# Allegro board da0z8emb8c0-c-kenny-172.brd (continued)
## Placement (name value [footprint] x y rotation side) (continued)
R444  *Short_0603  [S0603]  118.1 18.15 270 top
R445  *Short_0603  [S0603]  119.52 18.15 270 top
R446  *4.7K_5%_2  [R0201]  206.18 17.39 180 top
R448  *TPM@10K_1%_2  [R0201]  121.09 16.75 90 top
R450  *Short_0201  [S0201]  71.94 16.12 0 top
R451  4.7K_5%_2  [R0201]  204.66 17.39 180 top
R452  *TPM@0_5%_6  [R0603]  132.95 18.15 180 top
R453  *TPM@0_5%_6  [R0603]  132.95 19.67 180 top
R458  *TPM@33_5%_2  [R0201]  121.85 16.75 90 top
R459  100K_5%_2  [R0201]  183.58 18.53 0 top
R460  4.7K_5%_2  [R0201]  206.18 16.5 180 top
R461  *4.7K_5%_2  [R0201]  204.66 16.5 180 top
R462  100K_5%_2  [R0201]  164.02 17.26 90 top
R463  *10K_1%_2  [R0201]  127.44 16.12 180 top
R464  *GS@0_5%_2  [R0201]  67.96 18.15 180 top
R465  *4.7K_5%_2  [R0201]  204.66 15.61 180 top
R466  4.7K_5%_2  [R0201]  206.18 15.61 180 top
R468  *GS@10K_1%_2  [R0201]  67.56 15.73 0 top
R469  4.7K_5%_2  [R0201]  71.05 20.94 180 top
R470  *4.7K_5%_2  [R0201]  204.66 14.72 180 top
R471  4.7K_5%_2  [R0201]  206.18 14.72 180 top
R475  *GS@0_5%_2  [R0201]  67.78 14.87 90 top
R476  *4.7K_5%_2  [R0201]  204.66 13.83 180 top
R477  4.7K_5%_2  [R0201]  206.18 13.83 180 top
R481  4.7K_5%_2  [R0201]  204.66 12.81 180 top
R483  *GS@10K_1%_2  [R0201]  64.83 15.1 270 top
R484  *GS@0_5%_2  [R0201]  64.07 15.1 270 top
R485  *4.7K_5%_2  [R0201]  206.18 12.81 180 top
R486  *TPC@0_5%_2  [R0201]  11.31 11.8 0 top
R487  33_5%_2  [R0201]  183.58 15.1 0 top
R488  *Short_0201  [S0201]  203.13 14.59 180 top
R489  *TPC@0_5%_2  [R0201]  11.31 10.63 0 top
R492  *SSD@10K_5%_2  [R0201]  23.43 9 0 top
R497  *Short_0201  [S0201]  29.14 4.18 270 top
R498  *Short_0201  [S0201]  31.43 3.54 180 top
R500  *Short_0805  [S0805]  24.95 3.03 0 top
R501  *SSD@100K_1%_2  [R0201]  31.43 2.78 0 top
R507  2.2_5%_0603  [R0603]  43.37 121.53 0 bottom
R514  *Short_0201  [S0201]  39.69 115.18 0 bottom
R515  *Short_0805  [S0805]  64.45 109.59 270 top
R516  33_5%_2  [R0201]  59.14 109.92 270 top
R517  33_5%_2  [R0201]  56.15 105.02 90 bottom
R518  0_5%_6  [R0603]  58.99 104.84 270 bottom
R519  *0_5%_2  [R0201]  44.38 103.62 270 bottom
R520  *0_5%_2  [R0201]  45.15 103.62 270 bottom
R521  0_5%_2  [R0201]  46.42 105.02 270 bottom
R522  0_5%_2  [R0201]  47.18 105.02 270 bottom
R535  100K_1%_2  [R0201]  68.51 91.17 270 bottom
R536  *Short_0201  [S0201]  68.51 92.19 90 bottom
R551  *HUB@10K_4  [R0402]  95.18 91.3 270 bottom
R552  *HUB@10K_4  [R0402]  96.2 91.3 270 bottom
R554  *HDT@1K_1%_2  [R0201]  120.84 50.15 0 bottom
R556  *HUB@10K_4  [R0402]  100.52 88.89 180 bottom
R559  *HUB@100K_1%_4  [R0402]  101.15 87.49 90 bottom
R560  *HDT@10K_1%_2  [R0201]  120.84 47.87 180 bottom
R563  *HUB@10K_4  [R0402]  101.8 86.05 180 bottom
R566  *HUB@10K__5%_4  [R0402]  101.8 84.91 180 bottom
R567  *HDT@33_5%_2  [R0201]  111.85 43.04 90 bottom
R568  *HDT@1K_1%_2  [R0201]  117.89 47.61 180 top
R569  *HDT@1K_1%_2  [R0201]  117.89 45.83 180 top
R570  *0_5%_4  [R0402]  208.21 16.5 0 bottom
R571  *HUB@619_1%_4  [R0402]  93.28 82.92 270 bottom
R573  *33K_1%_4  [R0402]  212.13 15.48 0 bottom
R575  *HDT@10K_1%_2  [R0201]  120.94 46.34 180 bottom
R589  *150_1%_2  [R0201]  15.81 75.93 270 bottom
R595  *150_1%_2  [R0201]  16.06 81.9 270 bottom
R601  *150_1%_2  [R0201]  15.81 79.36 270 bottom
R606  *150_1%_2  [R0201]  15.81 77.71 270 bottom
R622  0_5%_2  [R0201]  19.24 57.39 0 bottom
R626  *HDT@1K_1%_2  [R0201]  111.44 49.26 180 bottom
R646  *0_5%_8  [R0805]  17.59 49.14 90 bottom
R649  *0_5%_8  [R0805]  21.78 49.14 90 bottom
R686  100K_5%_2  [R0201]  208.72 28.69 180 bottom
R690  *Short_0402  [S0402]  203.64 17.51 270 top
R691  *0_5%_2  [R0201]  209.74 31.1 0 top
R694  *0_5%_4  [R0402]  205.17 35.17 90 bottom
R695  *Short_0603  [S0603]  204.81 32.96 270 bottom
R697  *Short_0402  [S0402]  204.15 35.17 270 bottom
R698  *10K_1%_2  [R0201]  158.47 29.96 270 top
R699  *Short_0201  [S0201]  199.32 34.4 180 bottom
R700  *10K_1%_2  [R0201]  162.11 23.35 180 bottom
R706  *DBG@0_2  [R0201]  193.25 15.43 90 bottom
R707  22K_5%_2  [R0201]  200.34 34.4 180 bottom
R712  *DBG@0_2  [R0201]  192.54 15.43 90 bottom
R715  200K_1%_4  [R0402]  200.72 31.36 180 bottom
R718  10K_1%_2  [R0201]  201.23 34.53 270 bottom
R720  *0_5%_2  [R0201]  201.99 32.29 90 top
R730  MD@10K_5%_2  [R0201]  105.34 42.15 180 top
R731  MD@10K_5%_2  [R0201]  107.76 41.9 90 top
R732  MD@10K_5%_2  [R0201]  107.76 43.04 90 top
R734  100K_5%_2  [R0201]  199.99 32.37 90 bottom
R738  *Short_0805  [S0805]  189.67 29.7 180 top
R745  *Short_0201  [S0201]  195.26 23.61 90 bottom
R746  *0_5%_2  [R0201]  197.8 30.34 180 bottom
R749  22_5%_2  [R0201]  196.15 23.53 0 bottom
R751  33_5%_2  [R0201]  195.9 28.31 180 bottom
R752  *100K_1%_2  [R0201]  197.8 23.86 180 top
R754  *0_5%_2  [R0201]  197.8 29.58 180 bottom
R756  *3.3K_5%_2  [R0201]  197.93 31.1 180 bottom
R763  MD@10K_5%_2  [R0201]  106.23 41.9 90 top
R769  *0_5%_8  [R0805]  191.32 31.86 180 top
R772  *3.3K_5%_2  [R0201]  196.66 29.7 180 bottom
R773  *TPC@0_5%_6  [R0603]  32.57 18.27 90 top
R775  *TPC@10K_5%_2  [R0201]  31.43 17.64 270 top
R780  *Short_0603  [S0603]  199.83 19.87 180 top
R782  *Short_0201  [S0201]  197.8 28.82 0 bottom
R784  4.7K_5%_2  [R0201]  72.32 24.62 270 bottom
R785  *TPC@10K_5%_2  [R0201]  31.43 18.78 270 top
R787  4.7K_5%_2  [R0201]  75.5 24.62 270 bottom
R791  *10K_1%_2  [R0201]  168.34 21.07 0 bottom
R794  *2.2_5%_0603  [R0603]  167.57 23.74 0 bottom
R795  *10K_5%_2  [R0201]  67.12 22.44 90 bottom
R796  *Short_0201  [S0201]  68.01 22.21 180 bottom
R797  10K_5%_2  [R0201]  70.29 23.48 270 bottom
R798  *Short_0201  [S0201]  71.05 24.12 270 bottom
R802  *0_5%_2  [R0201]  192.59 19.67 90 bottom
R803  *2.2_5%_0603  [R0603]  164.94 23.74 180 bottom
R804  *PBA@0_5%_2  [R0201]  55.79 21.65 0 bottom
R805  4.7K_5%_2  [R0201]  174.22 32.12 90 top
R806  *10K_1%_2  [R0201]  124.27 17 180 bottom
R807  *Short_0201  [S0201]  70.42 25.77 0 bottom
R810  *0_5%_8  [R0805]  123.84 19.16 180 bottom
R811  4.7K_5%_2  [R0201]  173.09 32.42 0 top
R812  *33_5%_2  [R0201]  124.27 16.24 180 bottom
R816  4.7K_5%_2  [R0201]  181.29 18.53 180 bottom
R817  *TPC@10K_5%_2  [R0201]  26.35 18.27 270 top
R818  *TPC@0_5%_6  [R0603]  13.78 21.7 0 bottom
R819  *Short_0201  [S0201]  192.72 18.66 270 bottom
R820  *Short_0201  [S0201]  71.28 25.01 180 bottom
R824  *TPC@10K_5%_2  [R0201]  26.35 17.26 270 top
R825  *10K_1%_2  [R0201]  187.89 23.86 0 top
R827  *10K_1%_2  [R0201]  197.27 18.05 270 bottom
R828  *10K_1%_2  [R0201]  189.04 15.73 0 top
R830  *DBG@0_5%_2  [R0201]  192.72 17.64 90 bottom
R833  4.7K_5%_2  [R0201]  181.29 17.64 180 bottom
R834  GS_N@0_5%_2  [R0201]  212.41 17.39 180 bottom
R835  *GS@0_5%_2  [R0201]  212.41 16.62 180 bottom
R837  *Short_0201  [S0201]  212.28 13.96 90 bottom
R843  *Short_0201  [S0201]  32.22 11.64 90 bottom
R844  *Short_0201  [S0201]  32.98 11.64 90 bottom
R845  *Short_0201  [S0201]  35.22 11.64 90 bottom
R846  *Short_0201  [S0201]  35.98 11.64 90 bottom
R847  *Short_0201  [S0201]  26.22 11.54 90 bottom
R848  *Short_0201  [S0201]  26.99 11.54 90 bottom
R849  *Short_0201  [S0201]  29.22 11.54 90 bottom
R850  *Short_0201  [S0201]  29.98 11.54 90 bottom
R851  *Short_0201  [S0201]  38.24 11.54 90 bottom
R852  *Short_0201  [S0201]  39 11.54 90 bottom
R2211  *EV@5.1K_1%_2  [R0201]  120.97 120.38 270 top
R2212  *EV@5.1K_1%_2  [R0201]  121.6 125.08 270 top
R2213  EV@5.1K_1%_2  [R0201]  123.25 123.56 270 top
R2214  EV@5.1K_1%_2  [R0201]  122.49 121.02 270 top
R2215  EV@10K_5%_2  [R0201]  119.95 125.21 0 top
R2216  EV@10K_5%_2  [R0201]  120.08 122.54 0 top
R2217  EV@4.7K_5%_2  [R0201]  118.65 123.66 270 top
R2218  EV@5.1K_1%_2  [R0201]  120.97 122.03 270 top
R2219  EV@5.1K_1%_2  [R0201]  121.6 123.56 270 top
R2220  *EV@5.1K_1%_2  [R0201]  122.49 123.56 270 top
R2221  *EV@5.1K_1%_2  [R0201]  122.74 119.49 270 top
R2222  EV@10_1%_2  [R0201]  124.65 119.49 180 top
R2223  EV@49.9/F_2  [R0201]  124.52 121.78 90 top
R2226  EV@33_5%_2  [R0201]  119.95 124.45 180 top
R2227  EV@4.7K_5%_2  [R0201]  118.65 125.08 90 top
R2229  EV@10K_5%_2  [R0201]  113.85 118.99 90 top
R2230  EV@10K_5%_2  [R0201]  115.12 118.99 90 top
R2231  EV@33_5%_2  [R0201]  120.08 121.78 180 top
R2232  EV@5.1K_1%_2  [R0201]  124.65 118.73 180 top
R2236  EV@5.49K_1%_2  [R0201]  139.38 117.21 0 top
R2237  EV@2.37K_1%_2  [R0201]  141.29 116.95 180 top
R2238  EV@60.4_1%_2  [R0201]  142.17 113.4 180 top
R2239  EV@60.4_1%_2  [R0201]  142.17 112.64 180 top
R2240  EV@1K_1%_2  [R0201]  143.39 111.38 0 top
R2241  *Short_0201  [S0201]  95.82 100.95 180 top
R2242  *Short_0201  [S0201]  95.82 100.19 180 top
R2243  *Short_0201  [S0201]  95.82 99.43 180 top
R2253  EV@1K_1%_2  [R0201]  143.35 87.19 270 top
R2254  EV@60.4_1%_2  [R0201]  142.17 85.33 180 top
R2257  EV@60.4_1%_2  [R0201]  142.17 84.57 180 top
R2270  1K_1%_2  [R0201]  51.62 52.18 0 top
R2276  1K_1%_2  [R0201]  50.23 53.2 0 top
R2283  *0_5%_2  [R0201]  55.18 58.91 0 top
R2284  1K_1%_2  [R0201]  48.19 62.98 180 top
R2290  *1K_1%_2  [R0201]  51.88 67.68 0 top
R2300  240_1%_2  [R0201]  42.1 65.66 270 top
R2301  0_5%_2  [R0201]  42.94 65.66 90 top
R2302  39_1%_2  [R0201]  33.34 90.28 270 top
R2303  39_1%_2  [R0201]  31.81 90.28 270 top
R2304  39_1%_2  [R0201]  30.54 88.76 0 top
R2306  *0_5%_2  [R0201]  105.65 33.9 90 bottom
R2307  *Short_0201  [S0201]  104.91 33.64 270 bottom
R2308  10K_1%_2  [R0201]  105.85 35.17 90 bottom
R2309  10K_1%_2  [R0201]  114.49 39.99 180 top
R2310  *2K_1%_2  [R0201]  104.96 35.8 180 bottom
R2311  *2K_1%_2  [R0201]  114.49 39.23 0 top
R2313  39_1%_2  [R0201]  30.54 88 0 top
R2314  39_1%_2  [R0201]  32.57 90.28 270 top
R2315  39_1%_2  [R0201]  30.54 87.24 0 top
R2316  39_1%_2  [R0201]  34.1 90.28 270 top
R2317  39_1%_2  [R0201]  35.62 90.28 270 top
R2318  39_1%_2  [R0201]  36.38 90.28 270 top
R2319  39_1%_2  [R0201]  37.91 90.28 270 top
R2320  39_1%_2  [R0201]  37.15 90.28 270 top
R2321  39_1%_2  [R0201]  38.67 90.28 270 top
R2322  39_1%_2  [R0201]  39.43 90.28 270 top
R2328  39_1%_2  [R0201]  30.54 85.71 0 top
R2329  39_1%_2  [R0201]  30.54 84.95 0 top
R2330  39_1%_2  [R0201]  29.91 81.14 0 top
R2332  39_1%_2  [R0201]  30.54 81.9 0 top
R2334  39_1%_2  [R0201]  30.54 79.62 0 top
R2335  39_1%_2  [R0201]  30.54 80.38 0 top
R2336  39_1%_2  [R0201]  30.54 82.66 0 top
R2337  39_1%_2  [R0201]  30.54 83.43 0 top
R2338  240_1%_2  [R0201]  43.11 78.85 270 top
R2339  0_5%_2  [R0201]  45.02 78.09 180 top
R2342  39_1%_2  [R0201]  30.54 86.47 0 top
R2343  39_1%_2  [R0201]  34.86 90.28 270 top
R2344  *39_1%_2  [R0201]  33.84 77.96 0 top
R2346  *0_5%_2  [R0201]  37.78 78.78 180 top
R2347  39_1%_2  [R0201]  30.54 84.19 0 top
R2349  10K_5%_2  [R0201]  122.62 51.42 270 top
R2350  *10K_5%_2  [R0201]  122.62 52.44 270 top
R2351  10K_5%_2  [R0201]  121.85 51.8 270 top
R2352  *10K_5%_2  [R0201]  120.46 52.06 90 top
R2354  *10K_5%_2  [R0201]  120.58 51.93 0 bottom
R2355  10K_5%_2  [R0201]  120.58 51.17 0 bottom
R2357  10K_5%_2  [R0201]  87.18 34.66 270 bottom
R2358  10K_5%_2  [R0201]  88.71 33.77 270 bottom
R2359  *10K_5%_2  [R0201]  89.7 34.25 180 bottom
R2360  *10K_5%_2  [R0201]  90.82 33.77 180 bottom
R2361  10K_5%_2  [R0201]  91.37 35.8 0 bottom
R2362  *10K_5%_2  [R0201]  86.93 32.75 0 bottom
R2363  10K_5%_2  [R0201]  86.29 34.78 180 bottom
R2364  10K_5%_2  [R0201]  89.6 33.51 0 bottom
R2365  *10K_5%_2  [R0201]  90.56 34.66 270 bottom
R2376  *10K_5%_2  [R0201]  87.18 33.64 270 bottom
R2389  *Short_0603  [S0603]  50.73 50.41 90 top
R2390  100K_5%_2  [R0201]  116.77 36.56 0 top
R2391  *Short_0402  [S0402]  89.46 29.19 270 top
R2392  *Short_0402  [S0402]  81.09 25.51 270 top
R2393  *Short_0402  [S0402]  92.98 30.97 270 top
R2394  *Short_0402  [S0402]  82.1 25.51 270 top
R2395  10K_5%_2  [R0201]  103.69 32.24 90 top
R2396  470_1%_2  [R0201]  98.99 29.83 90 top
R2397  1K_1%_2  [R0201]  100.77 29.2 270 top
R2398  *Short_0402  [S0402]  93.99 31.74 270 top
R2399  *0_5%_2  [R0201]  96.71 34.28 0 top
R2400  47K_1%_2  [R0201]  91.27 27.72 270 bottom
R2401  *Short_0201  [S0201]  111.12 52.87 90 bottom
R2402  *Short_0201  [S0201]  111.89 52.87 90 bottom
R2403  *0_5%_2  [R0201]  106.36 34.15 270 bottom
R2404  1M_5%_2  [R0201]  105.98 38.59 90 bottom
R2406  8.2K_5%_4  [R0402]  115.25 36.56 180 top
R2407  *Short_0201  [S0201]  114.11 37.43 0 top
R2408  20M_5%_4  [R0402]  107.38 41.9 90 bottom
R2409  *Short_0603  [S0603]  117.03 42.53 270 top
R2410  *Short_0603  [S0603]  115.23 42.53 270 top
R2411  *Short_0603  [S0603]  102.68 37.58 0 top
R2412  *Short_0402  [S0402]  102.07 35.42 0 top
R2413  *Short_0201  [S0201]  110.3 52.87 90 bottom
R2416  *Short_0201  [S0201]  108.01 51.17 0 bottom
R2418  *Short_0201  [S0201]  108.01 50.41 0 bottom
R2419  *Short_0201  [S0201]  108.01 52.95 0 bottom
R2420  *Short_0201  [S0201]  108.01 52.18 0 bottom
R2421  33_5%_2  [R0201]  98.11 36.18 90 bottom
R2425  *10K_5%_2  [R0201]  101.79 35.17 180 bottom
R2426  33_5%_2  [R0201]  108.01 48.37 0 bottom
R2427  10K_5%_2  [R0201]  103.69 35.29 270 bottom
R2428  *TPM@10K_5%_2  [R0201]  120.89 23.48 0 top
R2429  33_5%_2  [R0201]  108.01 49.14 0 bottom
R2430  *10K_5%_2  [R0201]  104.96 35.04 180 bottom
R2431  *EV@0_5%_2  [R0201]  103.95 80.89 90 bottom
R2433  *Short_0201  [S0201]  109.54 52.87 90 bottom
R2438  10K_5%_2  [R0201]  95.29 28.64 270 top
R2439  *10K_5%_2  [R0201]  115.89 48.75 90 top
R2440  10K_5%_2  [R0201]  100.14 37.2 270 top
R2443  33_5%_2  [R0201]  108.01 47.64 0 bottom
R2444  *Short_0201  [S0201]  89.09 78.73 180 bottom
R2445  *10K_5%_2  [R0201]  102.8 35.17 0 bottom
R2446  33_5%_2  [R0201]  109.15 48.75 0 bottom
R2447  10K_5%_2  [R0201]  84.52 32.24 180 bottom
R2448  10K_5%_2  [R0201]  84.9 34.28 180 bottom
R2449  *10K_5%_2  [R0201]  87.36 30.14 270 top
R2450  10K_5%_2  [R0201]  83.75 34.28 180 bottom
R2451  *10K_5%_2  [R0201]  95.69 30.72 90 bottom
R2452  *Short_0201  [S0201]  115.12 48.75 270 top
R2453  2.2K_5%_2  [R0201]  71.94 15.35 180 top
R2454  2.2K_5%_2  [R0201]  70.93 15.35 180 top
R2455  10K_5%_2  [R0201]  87.56 31.23 180 bottom
R2462  33_5%_2  [R0201]  108.27 35.42 270 bottom
R2463  2.2K_5%_2  [R0201]  84.9 35.04 180 bottom
R2464  2.2K_5%_2  [R0201]  83.5 35.29 270 bottom
R2465  10K_5%_2  [R0201]  84.52 33.01 180 bottom
R2496  *Short_0201  [S0201]  90.49 78.35 90 bottom
R2499  1K_5%_2  [R0201]  107.12 74.66 270 bottom
R2502  *220_5%_2  [R0201]  94.93 78.98 90 bottom
R2503  *220_5%_2  [R0201]  110.55 46.46 0 bottom
R2505  *220_5%_2  [R0201]  96.07 78.98 90 bottom
R2508  *Short_0201  [S0201]  91.25 78.35 90 bottom
R2509  196_1%_4  [R0402]  103.82 58.91 180 top
R2510  *1K_1%_2  [R0201]  94.55 28.64 90 top
R2511  *1K_1%_2  [R0201]  93.91 77.96 180 bottom
R2512  *1K_1%_2  [R0201]  95.95 77.96 180 bottom
R2513  *1K_1%_2  [R0201]  94.93 77.96 180 bottom
R2514  *Short_0201  [S0201]  93.91 77.2 180 bottom
R2515  *Short_0201  [S0201]  95.95 77.2 180 bottom
R2516  *Short_0201  [S0201]  94.93 77.2 180 bottom
R2517  *Short_0201  [S0201]  109.13 46.46 180 bottom
R2519  300_5%_4  [R0402]  110.55 45.62 0 bottom
R2520  *1K_1%_2  [R0201]  89.09 77.96 0 bottom
R2521  *0_5%_2  [R0201]  89.09 77.2 0 bottom
R2522  2.2K_5%_4  [R0402]  104.84 77.58 270 bottom
R2523  1K_1%_2  [R0201]  92.01 78.35 90 bottom
R2524  1K_5%_2  [R0201]  100.85 75.86 270 top
R2525  *Short_0201  [S0201]  92.01 77.33 90 bottom
R2526  1K_5%_2  [R0201]  84.52 31.48 0 bottom
R2527  1K_5%_2  [R0201]  111.69 75.68 180 bottom
R2538  300_5%_4  [R0402]  110.55 44.64 0 bottom
R2543  *10K_1%_2  [R0201]  90.49 77.33 90 bottom
R2544  *10K_1%_2  [R0201]  92.9 77.96 0 bottom
R2545  *10K_1%_2  [R0201]  91.25 77.33 90 bottom
R2546  2.2K_5%_4  [R0402]  112.96 38.47 90 bottom
R2547  2.2K_5%_4  [R0402]  112.71 36.94 0 bottom
R2549  1K_1%_2  [R0201]  96 78.22 45 top
R2550  *1K_1%_2  [R0201]  96.58 77.71 45 top
R2551  *10K_1%_2  [R0201]  92.9 77.2 0 bottom
R2599  EV@10K_1%_2  [R0201]  108.52 120.26 0 bottom
R2600  *EV@5.1K_1%_2  [R0201]  109.79 120.26 180 bottom
R2601  EV@10K_5%_2  [R0201]  112.46 120.51 0 bottom
R2603  EV@5.1K_1%_2  [R0201]  112.46 119.75 0 bottom
R2604  *EV@5.1K_1%_2  [R0201]  113.73 122.8 180 bottom
R2605  *EV@5.1K_1%_2  [R0201]  113.73 119.75 180 bottom
R2606  *EV@5.1K_1%_2  [R0201]  113.73 121.27 180 bottom
R2607  *EV@5.1K_1%_2  [R0201]  115.25 121.27 0 bottom
R2608  EV@5.1K_1%_2  [R0201]  115.25 119.75 0 bottom
R2609  EV@5.1K_1%_2  [R0201]  116.52 121.27 180 bottom
R2610  *EV@5.1K_1%_2  [R0201]  116.52 119.75 180 bottom
R2611  EV@5.1K_1%_2  [R0201]  118.04 119.75 0 bottom
R2612  EV@5.1K_1%_2  [R0201]  118.04 121.27 0 bottom
R2613  EV@5.1K_1%_2  [R0201]  119.31 121.27 180 bottom
R2614  EV@5.1K_1%_2  [R0201]  119.31 119.75 180 bottom
R2615  EV@5.1K_1%_2  [R0201]  121.09 119.37 180 bottom
R2616  EV@5.1K_1%_2  [R0201]  124.39 119.37 180 bottom
R2618  *EV@10K_1%_2  [R0201]  108.39 119.37 0 bottom
R2619  EV@1K_1%_2  [R0201]  109.79 119.44 180 bottom
R2620  *EV@1K_1%_2  [R0201]  112.46 121.27 0 bottom
R2622  *EV@5.1K_1%_2  [R0201]  112.46 118.99 0 bottom
R2623  *EV@5.1K_1%_2  [R0201]  113.73 122.03 180 bottom
R2624  EV@5.1K_1%_2  [R0201]  113.73 118.99 180 bottom
R2625  EV@5.1K_1%_2  [R0201]  113.73 120.51 180 bottom
R2626  EV@5.1K_1%_2  [R0201]  115.25 120.51 0 bottom
R2627  *EV@5.1K_1%_2  [R0201]  115.25 118.99 0 bottom
R2629  EV@4.7K_5%_2  [R0201]  107.5 121.83 180 bottom
R2630  EV@4.7K_5%_2  [R0201]  109.54 122.34 0 bottom
R2631  *EV@10K_1%_2  [R0201]  106.61 120.48 90 bottom
R2632  *EV@5.1K_1%_2  [R0201]  116.52 120.51 180 bottom
R2633  EV@5.1K_1%_2  [R0201]  116.52 118.99 180 bottom
R2634  EV@5.1K_1%_2  [R0201]  118.04 118.99 0 bottom
R2635  EV@5.1K_1%_2  [R0201]  118.04 120.51 0 bottom
R2636  *EV@5.1K_1%_2  [R0201]  119.31 120.51 180 bottom
R2637  EV@5.1K_1%_2  [R0201]  119.31 118.99 180 bottom
R2638  *EV@5.1K_1%_2  [R0201]  121.09 118.6 180 bottom
R2639  *EV@5.1K_1%_2  [R0201]  124.39 118.6 180 bottom
R2640  EV@120_1%_4  [R0402]  137.22 120.64 180 bottom
R2641  EV@2.37K_1%_2  [R0201]  148.98 113.02 0 top
R2642  EV@5.49K_1%_2  [R0201]  148.98 114.03 180 top
R2643  *Short_0201  [S0201]  107.63 120.97 90 bottom
R2644  *Short_0201  [S0201]  108.49 121.02 0 bottom
R2645  EV@200_1%_2  [R0201]  106.61 118.99 90 bottom
R2648  EV@1M_1%_2  [R0201]  104.46 122.41 180 bottom
R2650  EV@5.1K_1%_2  [R0201]  102.17 119.24 270 bottom
R2651  *EV@5.1K_1%_2  [R0201]  103.19 119.24 90 bottom
R2652  EV@0_5%_2  [R0201]  104.58 119.11 0 bottom
R2653  *EV@16.2K_1%_4  [R0402]  97.6 118.48 180 bottom
R2654  EV@5.49K_1%_2  [R0201]  130.24 113.4 0 bottom
R2655  EV@2.37K_1%_2  [R0201]  130.24 114.16 0 bottom
R2656  EV@33_1%_2  [R0201]  117.92 121.14 270 top
R2657  EV@33_1%_2  [R0201]  117.92 122.16 270 top
R2660  EV@5.1K_1%_2  [R0201]  107.63 123.18 0 top
R2661  *EV@5.1K_1%_2  [R0201]  108.65 122.41 180 top
R2662  EV@120_1%_4  [R0402]  118.63 98.69 270 top
R2663  EV@1K_1%_2  [R0201]  140.67 102.24 180 bottom
R2664  EV@33_1%_2  [R0201]  108.65 123.18 0 top
R2665  EV@100_1%_2  [R0201]  118.04 101.33 90 top
R2666  EV@40.2_1%_2  [R0201]  118.04 100.32 90 top
R2667  *EV@5.1K_1%_2  [R0201]  107.63 124.83 0 top
R2668  EV@5.1K_1%_2  [R0201]  108.65 124.07 180 top
R2669  EV@33_1%_2  [R0201]  108.65 124.83 0 top
R2670  *EV@1K_1%_2  [R0201]  94.42 96.89 0 bottom
R2671  EV@1K_1%_2  [R0201]  140.79 97.39 180 bottom
R2672  *EV@1K_1%_2  [R0201]  95.57 96.89 0 bottom
R2673  EV@150_1%_2  [R0201]  96.71 98.16 180 bottom
R2674  EV@2.37K_1%_2  [R0201]  130.56 90.66 0 bottom
R2675  EV@5.49K_1%_2  [R0201]  130.56 89.47 0 bottom
R2677  2.37K_1%_2  [R0201]  145.25 79.77 90 bottom
R2678  EV@5.49K_1%_2  [R0201]  146.24 79.77 90 bottom
R2679  EV@120_1%_4  [R0402]  139.92 79.48 270 bottom
R2680  EV@5.49K_1%_2  [R0201]  142.05 79.65 90 bottom
R2681  EV@2.37K_1%_2  [R0201]  143.35 79.65 90 bottom
R2682  *0_5%_6  [R0603]  50.35 56.63 90 top
R2683  1K_1%_2  [R0201]  32.83 77.96 180 top
R2684  *0_5%_2  [R0201]  43.11 92.32 270 top
R2685  0_5%_2  [R0201]  37.78 78.04 0 top
R2687  *0_5%_2  [R0201]  37.65 67.3 180 top
R2688  0_5%_2  [R0201]  36.64 67.3 180 top
R2689  240_1%_2  [R0201]  41.21 43.04 180 top
R2690  0_5%_2  [R0201]  43.37 43.04 180 top
R2691  *0_5%_2  [R0201]  37.65 43.67 180 top
R2692  0_5%_2  [R0201]  36.64 43.67 180 top
R2693  240_1%_2  [R0201]  40.45 30.85 180 top
R2694  0_5%_2  [R0201]  41.46 30.85 180 top
R2695  *0_5%_2  [R0201]  36.95 32.24 0 top
R2696  0_5%_2  [R0201]  37.94 32.24 0 top
R2697  39_1%_2  [R0201]  40.32 78.98 180 top
R2698  39_1%_2  [R0201]  40.32 78.22 180 top
R2699  *Short_0201  [S0201]  16.83 77.33 0 bottom
R2700  *Short_0201  [S0201]  16.83 78.09 0 bottom
R2701  *Short_0201  [S0201]  16.83 78.98 0 bottom
R2702  *Short_0201  [S0201]  16.83 79.74 0 bottom
R2703  *Short_0201  [S0201]  17.08 81.52 0 bottom
R2704  *Short_0201  [S0201]  17.08 82.28 0 bottom
R2705  *Short_0201  [S0201]  16.83 75.55 0 bottom
R2706  *Short_0201  [S0201]  16.83 76.31 0 bottom
R2708  4.7K_5%_2  [R0201]  21.27 73.65 270 bottom
R2709  4.7K_5%_2  [R0201]  20.38 73.65 270 bottom
R2710  *4.7K_5%_2  [R0201]  21.65 77.46 270 top
R2711  *4.7K_5%_2  [R0201]  22.16 73.65 270 bottom
R2714  *MMC@100K_5%_2  [R0201]  67.63 33.51 0 bottom
R2717  EV@0.01_1%_1206  [R1206]  111.9 100.7 270 top
R2718  *EV@0.01_1%_1206  [R1206]  95.41 117.51 310 bottom
R2719  *TPC@10K_5%_4  [R0402]  24.57 15.35 0 top
R2720  *HUB@0_5%_2  [R0201]  98.36 81.14 90 bottom
R2721  *HUB@0_5%_2  [R0201]  97.6 81.14 90 bottom
R2722  *HUB@0_5%_2  [R0201]  90.23 91.3 270 bottom
R2723  *HUB@0_5%_4  [R0402]  101.41 80.89 0 bottom
R2724  *HUB@0_5%_4  [R0402]  100.01 80.12 270 bottom
R6024  *0_5%_4  [R0402]  65.59 26.78 90 bottom
R6507  *HUB@100K_1%_4  [R0402]  91.12 91.3 270 bottom
R6508  *HUB@47K__5%_4  [R0402]  92.14 91.3 90 bottom
R6510  *TPC@10K_5%_2  [R0201]  23.81 23.64 90 top
R6511  *short_0402  [S0402]  21.52 20.18 270 top
R6512  *TPC@10K_5%_4  [R0402]  20.38 20.18 90 top
R6513  *TPC@10K_5%_4  [R0402]  19.24 20.18 270 top
R6514  *TPC@0_5%_2  [R0201]  17.08 19.93 90 top
R6515  *TPC@220K_5%_2  [R0201]  12.89 17.26 270 bottom
R6516  *1TPC@0K_5%_4  [R0402]  18.1 20.18 270 top
R6517  *TPC@220K_5%_2  [R0201]  12.89 18.27 90 bottom
R6518  *TPC@220K_5%_2  [R0201]  13.4 15.48 90 top
R6519  *TPC@6.2K_1%_2  [R0201]  24.06 17.26 0 top
R6520  *TPC@220K_5%_2  [R0201]  13.4 14.46 270 top
R6521  *TPC@200K_1%_2  [R0201]  25.59 16.37 180 top
R6522  *TPC@750K_1%_2  [R0201]  16.95 11.42 0 top
R6523  *short_0402  [S0402]  24.45 12.94 180 top
R6524  *TPC@750K_1%_2  [R0201]  15.94 11.42 180 top
R6525  *TPC@750K_1%_2  [R0201]  15.81 13.58 0 top
R6526  *TPC@750K_1%_2  [R0201]  14.79 13.58 180 top
R6527  *TPC@10K_1%_2  [R0201]  24.06 16.37 0 top
R6528  *TPC@0_5%_2  [R0201]  24.83 23.86 0 top
R6529  *TPC@0_5%_2  [R0201]  25.08 19.67 0 top
R6530  *HUB@0_5%_4  [R0402]  97.22 91.3 270 bottom
R6532  0_5%_4  [R0402]  93.04 26.66 180 bottom
R6533  22_1%_4  [R0402]  81.47 24.12 180 bottom
R6534  22_1%_4  [R0402]  81.85 22.72 270 bottom
R6535  *10K_1%_2  [R0201]  81.47 25.13 0 bottom
R6536  22_1%_4  [R0402]  93.03 25.64 0 bottom
R6538  22_1%_4  [R0402]  93.03 24.62 0 bottom
R6540  *0_5%_2  [R0201]  102.68 34.4 0 bottom
R6541  *0_5%_2  [R0201]  100.87 35.93 0 bottom
R6542  *0_5%_2  [R0201]  99.93 35.96 270 bottom
R6543  *0_5%_2  [R0201]  99.07 36.1 0 bottom
R6544  10K_1%_2  [R0201]  93.03 27.55 0 bottom
R6550  *10K_1%_2  [R0201]  92.77 23.23 0 bottom
R6552  10_1%_2  [R0201]  92.9 31.1 0 bottom
R6553  10_1%_2  [R0201]  98.99 31.74 270 bottom
R6554  10_1%_2  [R0201]  99.12 33.21 0 bottom
R6555  10_1%_2  [R0201]  89.85 31.1 0 bottom
R6556  10_1%_2  [R0201]  90.87 31.1 0 bottom
R6557  10_1%_2  [R0201]  91.88 31.1 0 bottom
R6558  10_1%_2  [R0201]  93.91 31.1 0 bottom
R6559  10_1%_2  [R0201]  97.09 30.85 0 bottom
R6560  10_1%_2  [R0201]  97.09 31.86 270 bottom
R6563  *0_5%_2  [R0201]  161.35 21.07 270 top
R6564  0_5%_2  [R0201]  158.18 19.67 180 top
R6565  0_5%_2  [R0201]  156.65 20.43 180 top
R6566  0_5%_2  [R0201]  155.38 20.23 180 top
R6567  0_5%_2  [R0201]  162.88 24.14 180 top
R6568  0_5%_2  [R0201]  163 22.47 270 top
R6569  0_5%_2  [R0201]  183.58 27.04 0 top
R6570  0_5%_2  [R0201]  161.48 26.15 270 top
R6571  0_5%_2  [R0201]  163.26 25.79 180 top
R6572  0_5%_2  [R0201]  163.51 19.67 180 bottom
R6573  *0_5%_2  [R0201]  158.18 20.43 0 top
R6574  *0_5%_2  [R0201]  156.65 19.67 0 top
R6575  *0_5%_2  [R0201]  155.38 20.94 0 top
R6576  *0_5%_2  [R0201]  162.88 24.88 0 top
R6577  *0_5%_2  [R0201]  163.76 22.47 90 top
R6578  *0_5%_2  [R0201]  163.26 26.53 0 top
R6579  *MMC@10_1%_2  [R0201]  94.04 33.77 270 bottom
R6580  *MMC@10_1%_2  [R0201]  92.39 31.86 180 bottom
R6581  *MMC@10_1%_2  [R0201]  98.11 31.86 180 bottom
R6582  *MMC@10_1%_2  [R0201]  98.26 33.39 90 bottom
R6583  *MMC@10_1%_2  [R0201]  89.34 31.86 180 bottom
R6584  *MMC@10_1%_2  [R0201]  90.36 31.86 180 bottom
R6585  *MMC@10_1%_2  [R0201]  91.37 31.86 180 bottom
R6586  *MMC@10_1%_2  [R0201]  93.41 31.86 180 bottom
R6587  *MMC@10_1%_2  [R0201]  94.75 33.77 270 bottom
R6588  *MMC@10_1%_2  [R0201]  96.33 31.86 90 bottom
R6589  *MMC@10_1%_2  [R0201]  96.79 32.75 180 bottom
R6590  100K_1%_2  [R0201]  97.22 77.2 45 top
R6593  *0_5%_2  [R0201]  30.54 89.52 0 top
R6594  10K_1%_2  [R0201]  163 30.47 0 top
R6640  *0_5%_2  [R0201]  192.72 27.67 180 bottom
R6642  *0_5%_4  [R0402]  104.96 31.99 90 bottom
R6643  *Short_0201  [S0201]  49.34 105.9 180 top
R6644  1K_1%_2  [R0201]  73.72 53.2 180 bottom
R6645  *33K_1%_4  [R0402]  210.5 14.21 0 bottom
R6646  *Short_0402  [S0402]  210.09 18.15 90 bottom
R6647  *10K_5%_2  [R0201]  88.07 30.09 270 top
R6648  *Short_0201  [S0201]  103.44 84.19 180 bottom
R6650  200K_1%_2  [R0201]  99.38 37.2 90 top
R8041  *EV@5.1K_1%_2  [R0201]  120.84 125.08 90 top
R8042  *EV@5.1K_1%_2  [R0201]  122.49 122.44 270 top
R8046  *EV@5.1K_1%_2  [R0201]  120.84 123.56 270 top
R8047  *EV@5.1K_1%_2  [R0201]  123.25 122.44 90 top
R8053  EV@10K_1%_2  [R0201]  115.25 122.03 0 bottom
R8069  *EV@10K_5%_2  [R0201]  123.63 119.49 0 top
R8103  *EV@0_5%_2  [R0201]  125.79 122.41 270 top
R8104  *EV@4.7K_5%_2  [R0201]  125.66 120.76 180 top
R8107  EV@4.7K_5%_2  [R0201]  125.66 121.53 0 top
R8118  *EV@0_5%_2  [R0201]  108.52 122.34 180 bottom
R8122  EV@47K_1%_2  [R0201]  110.42 124.83 270 bottom
R8123  *EV@0_5%_2  [R0201]  110.42 123.81 90 bottom
R8128  *EV@0_5%_2  [R0201]  108.01 125.59 0 bottom
R8133  *EV@0_5%_2  [R0201]  82.61 89.7 90 bottom
R8134  *Short_0201  [S0201]  82.61 88.68 270 bottom
R8485  EV@10K_5%_2  [R0201]  124.14 88.63 180 bottom
R8527  *EV@10K_5%_2  [R0201]  105.85 120.48 270 bottom
R8533  *Short_0201  [S0201]  105.85 118.99 270 bottom
R12293  EV@4.7K_5%_2  [R0201]  128.84 122.29 0 top
R12295  *EV@0_5%_2  [R0201]  129.09 123.18 270 top
R12296  *EV@4.7K_5%_2  [R0201]  128.84 121.55 180 top
R12313  *HDT@1K_1%_2  [R0201]  111.44 50.41 0 bottom
R12314  *HDT@1K_1%_2  [R0201]  111.39 51.14 0 bottom
R12315  *HDT@0_5%_2  [R0201]  111.44 48.5 180 bottom
R12316  *HDT@33_5%_2  [R0201]  120.84 48.63 180 bottom
R12317  *HDT@10K_1%_2  [R0201]  120.94 47.1 180 bottom
R67418  *0_5%_2  [R0201]  19.87 38.09 180 bottom
R67855  *Short_0603  [S0603]  18.48 39.23 0 bottom
R67859  EV@1K_1%_2  [R0201]  95.57 98.92 0 bottom
R77817  R18M-50@8.45K_1%_4  [R0402]  96.71 103.62 0 bottom
R77818  R18M-50@2K_1%_4  [R0402]  96.71 101.59 180 bottom
R77819  R18M-50@6.98K_1%_4  [R0402]  96.71 104.63 0 bottom
R77820  R18M-50@4.99K_1%_4  [R0402]  96.71 105.65 180 bottom
R77821  R18M-50@4.75K_1%_4  [R0402]  96.71 114.54 180 bottom
R77822  *R18M-50@0_5%_4  [R0402]  96.75 112.46 0 bottom
R77825  *R18M-50@6.98K_1%_4  [R0402]  96.76 111.37 0 bottom
R77826  *R18M-50@4.75K_1%_4  [R0402]  96.76 109.33 180 bottom
R77827  EV@40.2_1%_2  [R0201]  113.98 96.13 0 top
R77828  EV@100_1%_2  [R0201]  113.98 97.65 180 top
R77829  *EV@0_5%_2  [R0201]  105.65 121.73 90 top
R77830  *EV@0_5%_2  [R0201]  104.71 123.15 0 top
R77831  *HUB@0_5%_4  [R0402]  94.17 91.3 270 bottom
R77832  EV@10K_5%_2  [R0201]  103.19 40.5 0 top
R77833  *EV@10K_5%_2  [R0201]  104.2 40.5 0 top
R77835  *HDT@0_5%_2  [R0201]  113.6 46.09 180 top
R77836  *0_5%_2  [R0201]  12.63 11.8 0 top
R77837  *0_5%_2  [R0201]  12.63 10.63 0 top
R77838  0_5%_2  [R0201]  13.09 11.8 180 top
R77839  0_5%_2  [R0201]  13.09 10.63 180 top
R77840  *0_5%_2  [R0201]  97.47 79.64 90 bottom
R77841  *0_5%_2  [R0201]  98.49 79.64 90 bottom
R77842  *0_5%_2  [R0201]  97.47 80.09 270 bottom
R77843  *0_5%_2  [R0201]  98.49 80.09 270 bottom
R77844  *PBA@0_5%_2  [R0201]  89.85 89.87 270 bottom
R77845  *PBA@0_5%_2  [R0201]  88.83 89.87 270 bottom
R77846  *PBA@0_5%_2  [R0201]  89.85 89.42 90 bottom
R77847  *PBA@0_5%_2  [R0201]  88.83 89.42 90 bottom
R77848  *HUB@0_5%_2  [R0201]  40.45 114.29 180 bottom
R77849  *HUB@0_5%_2  [R0201]  40.45 113.52 180 bottom
R77850  EV@100K_1%_4  [R0402]  118.04 125.34 0 bottom
R77851  *EV@0_5%_2  [R0201]  177.86 21.32 270 bottom
R77852  *Short_0201  [S0201]  177.86 20.31 270 bottom
R77853  *EV@5.1K_1%_2  [R0201]  112.58 119.75 0 top
R77854  EV@5.1K_1%_2  [R0201]  112.58 118.99 0 top
R77855  *EV@5.1K_1%_2  [R0201]  118.04 122.92 270 bottom
R77856  EV@5.1K_1%_2  [R0201]  117.92 122.03 0 bottom
R77857  10K_5%_2  [R0201]  103.69 34.4 180 bottom
R77859  *0_5%_2  [R0201]  109.03 16.12 180 top
R77861  *EV@10K_1%_2  [R0201]  106.61 120.48 270 top
R77862  *10K_5%_2  [R0201]  105.09 41.01 270 top
R77863  10K_5%_2  [R0201]  104.07 41.26 0 top
R77864  100K_5%_2  [R0201]  163.51 20.43 0 bottom
R77865  EV@100K_5%_2  [R0201]  110.93 119.37 180 top
R77866  100K_1%_2  [R0201]  67.37 94.35 270 bottom
R77867  *Short_0201  [S0201]  128.38 123.18 270 top
R77868  10K_5%_2  [R0201]  107.88 17.13 90 top
R77869  *10K_5%_2  [R0201]  111.95 18.53 0 top
R77870  *10K_5%_2  [R0201]  119.7 24.37 0 bottom
R77871  0_5%_2  [R0201]  119.31 25.13 180 bottom
R77872  *10K_5%_2  [R0201]  96.07 36.71 270 bottom
R77873  10K_5%_2  [R0201]  97.22 36.31 0 bottom
R77874  *Short_0201  [S0201]  39.56 116.32 0 bottom
R77875  *Short_0201  [S0201]  39.56 117.21 0 bottom
R77876  10K_5%_2  [R0201]  113.6 19.8 90 bottom
R77877  10K_1%_2  [R0201]  191.7 20.99 180 top
R77878  SSD@10K_1%_2  [R0201]  30.06 4.43 0 top
R77879  *TPM@10K_1%_2  [R0201]  121.85 23.4 90 top
R77880  *MMC@10K_4  [R0402]  94.04 30.21 0 bottom
R77881  2.2_5%_0603  [R0603]  170.24 23.74 180 bottom
R77882  10K_5%_2  [R0201]  97.12 36.31 270 top
R77883  10_1%_2  [R0201]  95.18 32.75 270 bottom
R77884  *Short_0201  [S0201]  205.55 26.78 0 top
RV1  *TPC@MESD3324PCR  [SON10-2_5X1-5-0_55H]  11.24 16.12 90 top
RV2  *TPC@MESD3324PCR  [SON10-2_5X1-5-0_55H]  11.24 16.12 270 bottom
RV8  *TPC@PESD5V0F1BSF  [D-0_6X0_3-0_32H-SMT]  10.09 11.92 0 top
RV9  *TPC@PESD5V0F1BSF  [D-0_6X0_3-0_32H-SMT]  10.09 10.65 0 top
SW1  *T3AL-23S-Q-T/R  [SW-T3AL-23-Q-TR-4P]  164.91 35.04 0 bottom
SW2  RESET_SW  [SW-TME-532-V-6P]  64.85 100.9 270 bottom
SW3  *NDT016-G1A-KKKT  [SW-NDT016-G1A-KKKT-4P]  19.1 60.62 180 bottom
TP2  *  [TP2050]  46.67 110.48 180 top
TP3  *  [TP2050]  46.92 109.08 180 top
TP4  *  [TP2050]  45.65 108.95 180 top
TP35  *TP  [TP2050]  168.92 32.55 0 top
TP36  *  [TP2050]  201.74 24.24 270 top
TP39  *TP  [TP2050]  163.76 27.8 0 top
TP41  *  [TP2050]  203.01 23.35 270 top
TP43  *TP  [TP2050]  182.65 24.56 0 top
TP44  *TP  [TP2050]  181.8 14.72 0 top
TP45  *PAD  [TP2050]  12.89 8.24 0 top
TP46  *TP  [TP2050]  172.91 12.18 0 top
TP47  *TP  [TP2050]  180.27 12.56 0 top
TP48  *TP  [TP2050]  166.3 14.08 0 top
TP49  *PAD  [TP2050]  17.64 4.84 0 top
TP68  *  [TP2075]  138.18 31.42 0 top
TP83  *PAD  [TP2050]  186.37 30.47 0 top
TP98  *PAD  [TP2050]  9.46 18.66 0 top
TP2023  *PAD  [TP2050]  60.39 53.2 180 bottom
TP2024  *PAD  [TP2050]  52 54.09 0 top
TP2025  *PAD_NC  [TP2050]  107.88 60.87 180 bottom
TP2026  *PAD_NC  [TP2050]  109.15 60.87 180 bottom
TP2027  *PAD_NC  [TP2050]  103.19 55.94 0 top
TP2028  *PAD_NC  [TP2050]  103.19 57.24 0 top
TP2032  *PAD_NC  [TP2050]  88.61 44.08 0 top
TP2038  *PAD_NC  [TP2050]  97.98 50.41 0 top
TP2039  *PAD_NC  [TP2050]  91.4 46.39 0 top
TP2044  *PAD_NC  [TP2050]  88.45 68.31 0 top
TP2045  *PAD_NC  [TP2050]  89.6 69.2 0 top
TP2050  *PAD_NC  [TP2050]  118.17 51.17 0 top
TP2051  *PAD_NC  [TP2050]  93.48 47.97 0 top
TP2052  *PAD_NC  [TP2050]  93.18 49.24 0 top
TP2053  *PAD_NC  [TP2050]  102.17 40.37 0 top
TP2054  *PAD_NC  [TP2050]  86.52 52.95 0 top
TP2055  *PAD_NC  [TP2050]  85.66 51.17 0 top
TP2056  *PAD_NC  [TP2050]  149.16 40.5 180 bottom
TP2089  *PAD  [TP2050]  101.29 83.89 180 bottom
TP2090  *PAD  [TP2050]  95.18 90.03 180 bottom
TP2091  *PAD  [TP2050]  102.56 83.89 180 bottom
TP8000  *PAD  [TP2050]  121.73 88.25 180 bottom
TP8001  *  [TP2650]  120.03 120.64 0 top
TP8002  *  [TP2650]  119.48 123.62 0 top
TP8006  *PAD  [TP2050]  117.66 123.05 0 top
TP8007  *  [TP2650]  109.79 118.6 180 bottom
TP8008  *PAD  [TP2050]  118.68 121.4 0 top
TP8009  *PAD  [TP2050]  97.09 98.67 0 top
TP8010  *  [TP2650]  108.27 118.53 180 bottom
TP8011  *PAD  [TP2050]  97.09 99.94 0 top
TP8012  *PAD  [TP2050]  107.76 122.41 0 top
TP8013  *PAD  [TP2050]  107.76 124.07 0 top
TP8067  *  [TP2650]  123 88.25 180 bottom
TP8068  *PAD  [TP2050]  111.57 120.38 180 bottom
TP8071  *PAD  [TP2050]  99.38 119.11 180 bottom
TP8073  *  [TP2650]  112.71 122.67 180 bottom
TP8074  *  [TP2650]  110.68 118.35 0 top
TP8075  *  [TP2650]  109.92 121.27 180 bottom
TP8076  *  [TP2650]  111.19 121.65 180 bottom
TP8527  *PAD  [TP2050]  111.64 118.86 180 bottom
TP8528  *PAD  [TP2050]  95.82 101.71 0 top
TP8529  *PAD  [TP2050]  123.76 118.73 0 top
TP8530  *PAD  [TP2050]  97.01 100.32 180 bottom
TP8531  *PAD  [TP2050]  97.09 101.71 180 top
TP8547  *PAD_NC  [TP2050]  111.19 40.75 180 bottom
TP8548  *PAD_NC  [TP2050]  111.82 39.61 180 bottom
TP9075  *PAD  [TP2650]  31.66 4.43 0 top
TP9078  *PAD  [TP2050]  43.75 93.2 0 top
TP9079  *PAD  [TP2050]  104.84 122.39 0 top
TP9081  *PAD  [TP2050]  95.69 100.32 180 bottom
TP9082  *TP  [TP2050]  165.16 22.72 180 bottom
TP9083  *TP  [TP2050]  171.33 31.36 0 top
TP9084  *TP  [TP2050]  174.48 31.15 0 top
TP9085  *PAD  [TP2050]  90.87 89.39 270 bottom
TP9086  *PAD  [TP2050]  92.14 89.39 270 bottom
TP9087  *TP  [TP2050]  182.69 28.13 0 top
TP9088  *TP  [TP2050]  163.64 33.64 0 top
TP9089  *  [TP2050]  68.51 117.84 0 top
TP9091  *  [TP2050]  117.16 50.41 0 top
TP9092  *  [TP2050]  96.31 49.26 0 top
TP9093  *  [TP2050]  144.21 52.56 180 bottom
TP9095  *TP  [TP2050]  167.45 20.94 180 bottom
TP9097  *PAD_NC  [TP2050]  103.57 36.38 180 bottom
TP9098  *PAD_NC  [TP2050]  101.03 39.61 0 top
TP9099  *PAD_NC  [TP2050]  17.08 18.91 0 top
TP9100  *PAD_NC  [TP2050]  95.82 36.23 0 top
TP9101  *TP  [TP2050]  158.81 23.1 180 bottom
TP9102  *TP  [TP2050]  161 33.26 0 top
TP9103  *TP  [TP2050]  182.69 21.45 0 top
TP9104  *PAD_NC  [TP2050]  110.81 42.02 180 bottom
TP9106  *PAD_NC  [TP2050]  91.88 36.94 180 bottom
TP9107  *PAD_NC  [TP2050]  90.33 35.9 180 bottom
TP9108  *PAD_NC  [TP2050]  90.61 37.15 180 bottom
TP9109  *PAD_NC  [TP2050]  87.95 34.1 180 bottom
TP9110  *PAD_NC  [TP2050]  89.47 34.96 180 bottom
TP9111  *PAD  [TP2050]  188.73 14.21 0 top
U1  RTL8111HSH-CG  [QFN32-4X4-4-33P-0_9H]  44.64 105.4 270 top
U5  USB30_ESD_AZ1065-06F.R7G  [DFN10-4_1X2-8-11P]  18.22 55.49 90 top
U7  SLGC55544CVTR  [QFN16-3X3-5-17P-TPS2546RTER]  20.13 48.63 0 top
U11  USB30_ESD_AZ1065-06F.R7G  [DFN10-4_1X2-8-11P]  18.86 35.29 90 top
U13  IT5571E-I-128/CX  [LQFP128-16X16-4-1_6H]  173.42 21.96 270 top
U15  *TPM@NPCT750AAAYX  [QFN32-5X5-5-33P-0_85H]  125.69 20.46 90 top
U16  *GS@LIS3DHTR  [LGA16-3X3-5]  65.16 18.2 0 top
U17  HDD_R@SN75LVCP601RTJR  [PWQFN20-4X4-5-26P-0_8H]  210.25 16.37 180 top
U21  NS892407  [TRF-N1010G-25P]  32.4 107.58 180 bottom
U23  G524B1T11U  [TSOT23-2_8-95-5P-G916-475TOUF]  66.48 91.55 90 bottom
U26  PS8203  [TQFN32-3X6-4-41P-0_8H]  20.25 78.47 270 bottom
U28  G524B2T11U  [SOT23-5-2_8-95-5P-G708]  19.87 44.18 180 bottom
U30  ALC255-CG  [QFN48-6X6-4-49P-ALC280]  203.13 26.66 90 bottom
U33  W25X10CLSNIG  [SOIC8-6-1_27-PM25LV010A]  161.1 28.84 180 bottom
U35  G524B2T11U  [SOT23-5-2_8-95-5P-G708]  211.11 21.6 90 bottom
U2013  MD@DDR4_96P  [BGA96-MICRON-MT41J64M16JT-187EG]  40.13 37.35 270 top
U2014  MD@DDR4_96P  [BGA96-MICRON-MT41J64M16JT-187EG]  40.13 48.73 270 top
U2017  MD@DDR4_96P  [BGA96-MICRON-MT41J64M16JT-187EG]  40.13 72.33 270 top
U2018  MD@DDR4_96P  [BGA96-MICRON-MT41J64M16JT-187EG]  40.13 83.71 270 top
U2021  AP2138N-1.5TRG1  [SOT23-2_38-95-3P]  97.47 27.67 270 top
U2028  *EV@MX25L2006EM1I-12G  [SOIC8-6-1_27-PM25LV010A]  113.22 122.8 270 top
U2029  EV@R17M-P1-70  [BGA769-AMD-FT3]  112 103.72 180 bottom
U2030  FP5  [BGA1140-AMD-FP5]  90.51 57.01 270 bottom
U2031  *MMC@KLMBG2JETD-B041  [BGA153-SANDISK-SDIN7DP4-16G]  66.86 32.63 90 top
U2032  *PTN36001  [QFN12-1_25X2_1-4]  29.02 18.15 0 top
U2033  *HUB@GL852G-OHY60  [QFN28-5X5-5-29P-GL850G]  96.71 85.84 180 bottom
U2034  *TPC@RTS5441E-GR  [QFN24-4X4-5-25P-RT9921CGQV]  19.87 15.61 270 top
U2035  *TPC@G518A1TO1U  [SOT23-2_8-95-5P-G518A1TO1U]  16.44 24.12 180 bottom
U2038  W25Q64FWSSIG  [SOIC8-7_9-1_27-2_16H]  87.31 24.75 270 bottom
U2039  *74LVC1G17GW  [SOT353-1-2_125-65-5P]  193.43 24.62 90 bottom
U5400  G781-1P8  [MSOP8-4_9-65-G547]  18.73 33.9 0 bottom
U8001  EV@TC7SH08FU(F)  [SOT353-1-2_125-65-5P]  84.26 88.17 270 bottom
U8021  EV@Si51214-A1EAGM  [DFN6-1_4X1_2-4]  104.58 120.64 90 bottom
U8022  *HDT@SN74LVC2G07DCKR  [SC70-2_1-65-6P-0_95H]  115.73 46.72 180 top
U8023  EV@TC7SH08FU(F)  [SOT353-1-2_125-65-5P]  114.62 124.7 180 bottom
VC1  *TVM0G5R5M220R  [C0402]  15.94 88.63 90 top
VRAM2001  EV@GDDR5  [BGA170-MICRON-MT51J256M32HF]  140.38 110.98 180 bottom
VRAM2002  EV@GDDR5  [BGA170-MICRON-MT51J256M32HF]  140.38 88.59 0 bottom
Y1  25MHZ/30ppm  [XTL-2_05X1_65-1_4X1_1-0_6H]  44.64 112.64 180 top
Y2002  48MHZ/15ppm  [XTL-3_2X2_5-2_2X1_8-4P]  108.9 38.09 270 bottom
Y2003  32.768KHZ/20ppm  [XTL-3_2X1_5-2_5-SMT]  108.9 41.9 270 bottom
Y2004  EV@27MHZ/10ppm  [XTL-3_2X2_5-2_2X1_6-0_9H]  104.07 124.45 0 bottom
Y2005  *HUB@12MHz  [XTL-3_2X2_5-2_2X1_8-4P]  89.22 85.71 90 bottom

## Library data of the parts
C17 C22-C25 C28-C33 C37 C39 C42 C43 C45 C51 C53 C58 C61 C62 C64 C65 C88 C93 C94 C106 C113 C146-C150 C180-C183 C205 C210 C212 C222 C239 C249 C270 C272 C277 C280 C287 C295 C304 C310 C328 C345 C349 C351 C352 C363-C365 C368 C372 C386 C388 C394 C395 C400-C412 C414-C424 C426-C431 C436 C438 C439 C442 C443 C447 C449-C451 C454 C460-C462 C465 C466 C468-C471 C476-C479 C489-C491 C498 C508 C525-C531 C533-C538 C542 C545 C549-C551 C558 C560 C593 C599 C604 C608-C610 C612 C615 C622 C644-C646 C670-C676 C679-C682 C684 C695 C698-C700 C707 C711 C715-C718 C869 C926 C1104 C2195-C2199 C2207-C2215 C2217-C2219 C2221 C2223-C2225 C2227-C2229 C2231-C2238 C2240-C2245 C2247-C2250 C2252-C2260 C2263 C2266-C2270 C2272 C2274-C2277 C2279-C2281 C2283 C2285-C2291 C2295-C2298 C2304-C2308 C2310-C2313 C2315-C2323 C2340-C2347 C2349 C2350 C2352 C2368 C2369 C2375-C2381 C2385 C2387-C2396 C2405 C2406 C2412 C2418 C2431 C2464-C2467 C2469-C2517 C2522-C2539 C2545-C2553 C2567-C2569 C2573-C2580 C2593 C2594 C2596 C2631-C2641 C2646-C2654 C2661 C2665-C2669 C2674 C2678-C2690 C2693-C2704 C2707-C2730 C2733 C2736-C2745 C2770-C2781 C2783 C2786 C2787 C8110 C8116 C8118 C8126 C8127 C8132-C8134 C8164 C8165 C28052-C28055 C28062 C28063 C28066 C28067 C96269 C96274 C96275 EC5 EC9 EC2007 EC2008 PC104 PC135 PC164 PC2016 PC2017 PC5357 PC5359 PC6000 PC6005-PC6007 PC6011 PC6012 PC6014 PC6015 PC9005-PC9007 PC9009 PC9011-PC9013 PC9015 PC9016 PC9027 PC9029 PC9038 PC9040 PC9047 PC9065-PC9080 PC9091 PC9092 PC9094-PC9096 PC9173-PC9179 PC9181-PC9183 PC9185-PC9192 VC1 = CAP_NON-POL_BGM
C67 C91 C97 C112 C323 C327 C332-C334 C340 C343 C366 C367 C371 C375 C377-C379 C381 C384 C385 C387 C389-C393 C396-C399 C413 C425 C432-C435 C437 C440 C441 C445 C446 C453 C455-C459 C464 C467 C480 C532 C539-C541 C559 C616 C619 C620 C623 C624 C627 C629 C635 C637 C638 C641 C643 C647 C648 C650 C656 C659-C661 C663 C666 C667 C683 C685-C694 C696 C697 C701 C703-C705 C708 C710 C713 C714 C719 C2185 C2216 C2351 C2384 C2386 C2403 C2410 C2416 C2434 C2448 C2655-C2658 C2662 C2671-C2673 C2691 C2692 C2705 C2706 C2731 C2732 C2768 C2769 C2782 C2784 C2785 C2788 C8115 C8155 C96270-C96272 EC3 EC4 EC8 PC2000-PC2015 PC6001-PC6004 PC6008-PC6010 PC6013 PC6016-PC6025 PC6031-PC6052 PC6055-PC6065 PC9000-PC9004 PC9008 PC9010 PC9014 PC9017-PC9025 PC9031-PC9036 PC9041-PC9046 PC9050 = CAP NON-POL_BGM
C370 C2790 = CAP_NON-POL_BGM: tolerance: CH4103K9E01
C373 C2792 PC574 PC9162 = CAP_NON-POL_BGM: tolerance: CH02206JB08
C374 = CAP_NON-POL_BGM: tolerance: CH5101K9E02
C2239 C2246 C2251 C2261 C2262 C2264 C2265 C2273 C2278 C2282 C2663 C2670 C2757-C2759 C2762 C2764 C2789 = C
C2271 = CAPACITOR POL_4
C2660 = CAP NP_4
C2760 C2761 C2763 = CAP NP
C2765 C2766 = C_0
C2767 PC1 PC125 PC126 PC234 PC265 = CAP_NON-POL_BGM: tolerance: CH5102K9B06
CN1 = HEADER_4P_50208-00401-V02_BGM
CN2 = FFCFPC_40P_BGM
CN3 = RJ45_8P_4fix_V3_BGM
CN4 = HDMI_19P_10444-19001_BGM
CN5 CN7 = HEADER 4_0
CN6 = FFCFPC_40P_BGM_0
CN8 CN10 = FFCFPC_28P_BGM
CN9 = NGFF_79P_EKEY_NAME_BGM
CN11 CN16 = FFCFPC_4P_BGM
CN12 CN13 = FFCFPC_8P_BGM
CN14 = USB3_1_24P_8F_V5_BGM
CN15 = FFCFPC_18P_BGM
CN17 = FFCFPC_6P_BGM
CN18 = NGFF_79P_MKEY_NAME_BGM
CN2019 = DDR3_5
CN2020 = Header_2P_BGM
CN2021 = Header_20P_2R_WOFIXP_BGM
D1 D34 D35 = DIODE_BGM
D3 D4 D16-D18 D21 D22 D24-D32 EC6 EC7 RV8 RV9 = TVS_DIODE_BGM
D5 D2025 D6542 D6543 = BAT54A_BGM
D8 D9 D11-D15 D36 D37 D2024 D2026 D2038-D2040 D8510 D8514-D8516 = Schottky_DIODE_BGM
D10 D19 D38 D39 D41 = Varistor_BGM
D2021 = BAT54C_BGM
D8001 D8509 = 1N4148
D8511-D8513 = DIODE_BGM: tolerance: BC1N4148Z00
FAN1 = Header_4P_BGM
FB104 PL2000 PL6000-PL6002 PL9000-PL9002 PL9005 PL9006 = INDUCTOR_BGM
HD1 = FFCFPC_12P_V1_BGM
HE1 HE2 = HALL_IC_3P_BGM
HOLE2 HOLE3 HOLE5-HOLE8 HOLE13 HOLE14 HOLE17 HOLE19-HOLE21 HOLE24-HOLE26 = 3x2_1.1: tolerance: MBZ8P003010
HOLE10 HOLE15 = 3x2_1.1: tolerance: MBZAU001010
HOLE11 HOLE16 HOLE18 HOLE22 HOLE23 = 3x2_0.1: tolerance: *
J1 = OPEN
L6 L7 L9-L16 = BEAD_BGM
PC2 = CAP_NON-POL_BGM: tolerance: CH6102M9B00
PC3 PC10 PC139 PC248 PC253 PC254 = CAP_NON-POL_BGM: tolerance: CH4104K1B00
PC6 PC243 = CAP_NON-POL_BGM: tolerance: CH34706K912
PC7 PC66 PC67 PC69 PC113 PC114 PC119-PC121 PC128-PC133 PC137 PC224-PC226 PC269 PC562 PC563 PC9163 = CAP_NON-POL_BGM: tolerance: CH6221M9900
PC8 PC92 PC98 PC110 PC111 = CAP_NON-POL_BGM: tolerance: CH21006JB10
PC11 PC12 PC140 = CAP_NON-POL_BGM: tolerance: CH6104M9901
PC14 PC86 PC117 PC138 PC221 PC236 PC261 = CAP_NON-POL_BGM: tolerance: CH22206KB16
PC15 = CAP_NON-POL_BGM: tolerance: CH4472K9B00
PC16 PC18 PC142 PC571 = CAP_NON-POL_BGM: tolerance: CH6101M9B02
PC70 PC272 = CAP_NON-POL_BGM: tolerance: CH01006JB08
PC71 PC72 PC78 PC79 PC87 PC93 PC99 PC103 PC108 PC109 PC242 PC250-PC252 PC267 PC268 PC271 PC6231 = CAP_NON-POL_BGM: tolerance: CH4103K1B08
PC73 PC77 PC235 PC258 = CAP_NON-POL_BGM: tolerance: CH11006JB00
PC74 PC76 PC237 = CAP_NON-POL_BGM: tolerance: CH4106K9B01
PC80 = CAP_NON-POL_BGM: tolerance: CH5222K9B06
PC81 PC105 PC106 PC112 PC6230 PC9132 = CAP_NON-POL_BGM: tolerance: CH6101M9905
PC82 PC88 PC90 PC101 = CAP_NON-POL_BGM: tolerance: CH5104K9B01
PC91 PC96 PC572 = CAP_NON-POL_BGM: tolerance: CH31006KB18
PC115 PC136 PC247 PC249 = CAP_NON-POL_BGM: tolerance: CH16806J911
PC116 PC229 PC244 PC245 PC262 PC263 = CAP_NON-POL_BGM: tolerance: CH4104K9B03
PC118 PC143 PC145 PC256 = CAP_NON-POL_BGM: tolerance: CH4106K1B01
PC122 PC123 = CAP_NON-POL_BGM: tolerance: CH04706JB01
PC227 = CAP_NON-POL_BGM: tolerance: CH5471K9B00
PC233 PC239 PC240 PC264 PC270 = CAP_NON-POL_BGM: tolerance: CH6104K9A00
PC238 = CAP_NON-POL_BGM: tolerance: CH4474K1907
PC241 PC246 = CAP_NON-POL_BGM: tolerance: CH6224M9A00
PC266 = CAP_NON-POL_BGM: tolerance: CH5472K9901
PC551 = CAP_NON-POL_BGM: tolerance: CH22206K917
PC561 PC581 = CAP_NON-POL_BGM: tolerance: CH4101K9E01
PC6026-PC6030 PC6053 PC6054 PC9026 PC9028 PC9037 PC9039 PC9049 = CAP_POL_BGM
PC6229 = CAP_NON-POL_BGM: tolerance: CH4471K9B03
PC9164 = CAP_NON-POL_BGM: tolerance: CH5471M9B00
PD2 = ZENER_DIODE_BGM: tolerance: BCAFJ20AZ00
PD4 = BAT54C_BGM: tolerance: BCBAT54CZ13
PD5 PD6 = ZENER_DIODE_BGM: tolerance: BDPDZ56BZ07
PJ1 PJ5 PR6 PR68 PR87 PR99 PR107 PR110 PR111 PR117 PR127 PR130 PR156 PR254 PR6014 PR6033 PR6043 PR9010 PR9031 PR9040 PR9108 PR9282 PR77848 R4 R38 R442-R445 R500 R515 R695 R738 R780 R2389 R2409-R2411 R67855 = SHORTPAD_V01_BGM
PJ2-PJ4 PJ2000 PJ2001 PJ7002 PJ7004 PJ7005 PJ9001 PJ9007 PJ9008 PJ9010 = R_Current_SEN_BGM
PJ6 = DCJACK_30706-00042-001_BGM: tolerance: DFPJ03MR149
PJ11 = HEADER_8P_2F_BGM: tolerance: DFHD08MR201
PL1 = INDUCTOR_BGM: tolerance: CV-4712MZ10
PL2 = INDUCTOR_BGM: tolerance: CV+68F5MZ05
PL10 PL13 = INDUCTOR_BGM: tolerance: CV-10B0MZ13
PL11 = INDUCTOR_BGM: tolerance: CV-6845MZ05
PL14 = INDUCTOR_BGM: tolerance: CV-2219MZ02
PL551 = INDUCTOR_BGM: tolerance: CV-1037MZ00
PQ3 PQ4 PQ6003 = MOS-N_8P_BGM
PQ7 PQ10 PQ35 PQ9006-PQ9008 PQ9013 PQ9015 PQ9057 PQ9062 PQ9063 PQ9065-PQ9069 Q6 Q7 Q18 Q20 Q43 Q45 Q46 Q2025 Q2033 Q2039 Q5403 = MOS-N_3P_ESD_BGM
PQ8 Q3 Q44 = DTC144EU_BGM
PQ9 = MOS-N_3P_ESD_BGM: tolerance: BAM70020041
PQ11 = MOS-N_8P_BGM: tolerance: BAM32300000
PQ12 PQ13 = MOS-N_3P_ESD_BGM: tolerance: BAM70020002
PQ26 PQ27 PQ2000 PQ6000 = MOS-N_8P_V3_BGM
PQ6001 PQ6002 PQ9000 PQ9001 = MOS-N-Dual_10P_BGM
PQ9002 = MOS-N-Dual_9P_BGM
PQ9003 Q2 Q19 Q47 = MOS-P_3P_BGM
PQ9014 PQ9056 = MOS-N_3P_ESD_V3_BGM
PR2 PR9 PR161 PR566 PR2009 PR2013 PR6002 PR6028 PR6056 PR6417 PR9002 PR9053 PR9117 PR9118 PR9310 PR77835 PR77853 PR77858 PR77862 PR77864 R336 R344 R374 R464 R690 R697 R804 R2391-R2394 R2398 R2412 R2720-R2722 R6646 R77871 = SHORTPAD_BGM
PR8 PR18 PR19 PR77 PR80 PR86 PR88 PR89 PR92 PR93 PR96 PR100 PR112 PR121 PR122 PR124-PR126 PR128 PR193 PR237 PR244 PR249-PR251 PR253 PR255 PR257 PR259-PR261 PR267 PR270 PR271 PR273 PR276 PR284 PR2004-PR2006 PR2012 PR6000 PR6012 PR6021 PR6030 PR6032 PR6037 PR6039 PR6041 PR6044 PR6049 PR6051 PR6061 PR6068 PR6069 PR6071 PR6072 PR6074 PR6075 PR9015 PR9018 PR9034 PR9036 PR9038 PR9041 PR9046 PR9048 PR9055 PR9059 PR9066 PR9067 PR9069 PR9070 PR9072 PR9073 PR9104 PR9105 PR9116 PR9119 PR9124 PR9290 PR9292 PR9296 PR77849 R20 R28 R33 R98 R198 R200 R280 R281 R284 R293 R298 R319-R322 R345 R366 R375 R416 R437 R450 R488 R497 R498 R514 R536 R699 R745 R782 R796 R798 R807 R819 R820 R837 R843-R852 R2241-R2243 R2307 R2401 R2402 R2407 R2413 R2416 R2418-R2420 R2433 R2444 R2452 R2496 R2508 R2514-R2517 R2525 R2643 R2644 R2699-R2706 R6643 R6648 R8134 R8533 R77852 R77867 R77874 R77875 R77884 = RES_BGM: tolerance: CS00001JE18
PR12 PR266 = R_Current_SEN_BGM: tolerance: CS+0108FP01
PR69 PR71 = RES_BGM: tolerance: CS51003J936
PR70 PR83 PR84 PR275 PR279 PR567 = RES_BGM: tolerance: CS31002FB26
PR72 PR78 PR274 PR278 = RES_BGM: tolerance: CS21002FB24
PR74 PR75 PR97 R324 R351 R77850 = RES_BGM: tolerance: CS41002FB28
PR76 = RES_BGM: tolerance: CS32052FB21
PR81 = RES_BGM: tolerance: CS02006J201
PR82 PR102 PR118 PR131 PR159 PR160 PR191 PR216 PR230 PR234 PR283 PR568 PR2000-PR2003 PR2007 PR2008 PR2010 PR2011 PR2015 PR2033 PR6001 PR6003-PR6011 PR6013 PR6015-PR6017 PR6019 PR6020 PR6022-PR6024 PR6026 PR6027 PR6029 PR6031 PR6034-PR6036 PR6038 PR6040 PR6042 PR6045-PR6048 PR6050 PR6052-PR6055 PR6058-PR6060 PR6062-PR6064 PR6066 PR6067 PR6070 PR6073 PR9000 PR9001 PR9003-PR9009 PR9011-PR9014 PR9016 PR9017 PR9020-PR9024 PR9026-PR9030 PR9033 PR9035 PR9037 PR9039 PR9042-PR9045 PR9047 PR9049-PR9052 PR9056-PR9058 PR9060-PR9062 PR9064 PR9065 PR9068 PR9071 PR9100-PR9103 PR9106 PR9107 PR9120-PR9123 PR9125 PR9126 PR9128 PR9129 PR9133-PR9137 PR9284-PR9289 PR9295 PR9298 PR9300 PR9301 PR9304 PR9311 PR77846 PR77850-PR77852 PR77854 PR77855 PR77857 PR77859-PR77861 PR77863 PR77865 PR77866 R5-R16 R18 R19 R21-R27 R30-R32 R34 R37 R39 R41 R44 R52 R55 R93 R104 R106 R107 R128-R131 R163 R164 R210 R211 R217 R218 R222-R225 R227 R234 R235 R244 R246-R249 R251 R252 R257 R260 R264 R275 R289 R309 R310 R314 R315 R318 R331 R333 R338 R355 R360 R362 R364 R365 R368-R371 R376 R385 R389 R392 R393 R399-R403 R407 R410-R412 R417-R423 R429-R432 R435 R436 R438 R440 R441 R446 R448 R451-R453 R458 R460 R461 R463 R465 R466 R468-R471 R475-R477 R481 R483-R487 R489 R492 R501 R507 R516-R522 R535 R554 R560 R567-R570 R573 R575 R589 R595 R601 R606 R622 R626 R646 R649 R686 R691 R698 R700 R706 R707 R712 R715 R718 R720 R730-R732 R734 R746 R749 R751 R752 R754 R756 R763 R769 R772 R773 R775 R784 R785 R787 R794 R795 R797 R802 R803 R805 R806 R810-R812 R816-R818 R824 R825 R827 R828 R830 R833-R835 R2217 R2222 R2227 R2270 R2276 R2283 R2284 R2290 R2300-R2304 R2306 R2308-R2311 R2313-R2322 R2328-R2330 R2332 R2334-R2339 R2342-R2344 R2346 R2347 R2349-R2352 R2354 R2355 R2357-R2365 R2376 R2390 R2395-R2397 R2399 R2400 R2403 R2404 R2406 R2408 R2421 R2425-R2431 R2438-R2440 R2443 R2445-R2451 R2453-R2455 R2462-R2465 R2499 R2502 R2503 R2505 R2509-R2513 R2519-R2524 R2526 R2527 R2538 R2543-R2547 R2549-R2551 R2629 R2630 R2670 R2672 R2682-R2685 R2687-R2698 R2708-R2711 R2714 R2719 R2723 R2724 R6024 R6510-R6530 R6535 R6540-R6544 R6550 R6552-R6560 R6563-R6590 R6593 R6594 R6640 R6642 R6644 R6645 R6647 R6650 R8485 R12313-R12317 R67418 R67859 R77817-R77822 R77825 R77826 R77831 R77835-R77849 R77857 R77859 R77862 R77863 R77866 R77868-R77870 R77872 R77873 R77876-R77879 R77881-R77883 = RES_BGM
PR85 = RES_BGM: tolerance: CS41002JB20
PR90 = RES_BGM: tolerance: CS51002JB21
PR98 = RES_BGM: tolerance: CS43162FB00
PR108 PR115 PR239 = RES_BGM: tolerance: CS01003F935
PR113 PR119 PR120 = RES_BGM: tolerance: CS11002JB32
PR114 PR129 PR258 PR268 = RES_BGM: tolerance: CS-4703J917
PR123 PR236 PR277 PR569 PR6414 = SHORTPAD_V01_BGM: tolerance: TMPSHT00201
PR132 = RES_BGM: tolerance: CS-5103F916
PR194 = RES_BGM: tolerance: CS33242FB19
PR245 = RES_BGM: tolerance: CS48662FB00
PR246 = RES_BGM: tolerance: CS41372FB12
PR247 PR248 = RES_BGM: tolerance: CS24022FB13
PR252 PR6416 PR9283 = RES_BGM: tolerance: CS41001FE08
PR264 PR265 = RES_BGM: tolerance: CS31002JB28
PR551 = RES_BGM: tolerance: CS-2203J913
PR6018 PR6025 PR6057 PR6065 PR9019 PR9025 PR9054 PR9063 = Thermistor_BGM
PR6418 = RES_BGM: tolerance: CS32262FB15
PR9032 PR9305 PR9306 PR9308 PR9309 = SRES_BGM
PR9132 PR77847 = RES_BGM_R0402_EV@100K_1%_4
PU1 = TPS51486XRJER_18P_BGM: tolerance: AL051486000
PU6 PU7 = AOZ1331ADI_14P_BGM
PU9 = UP8801SSW8_8P_BGM
PU11 = RT6256BGQUF_12P_BGM: tolerance: AL006256000
PU12 = BQ24780SRUYR_BGM: tolerance: AL024780001
